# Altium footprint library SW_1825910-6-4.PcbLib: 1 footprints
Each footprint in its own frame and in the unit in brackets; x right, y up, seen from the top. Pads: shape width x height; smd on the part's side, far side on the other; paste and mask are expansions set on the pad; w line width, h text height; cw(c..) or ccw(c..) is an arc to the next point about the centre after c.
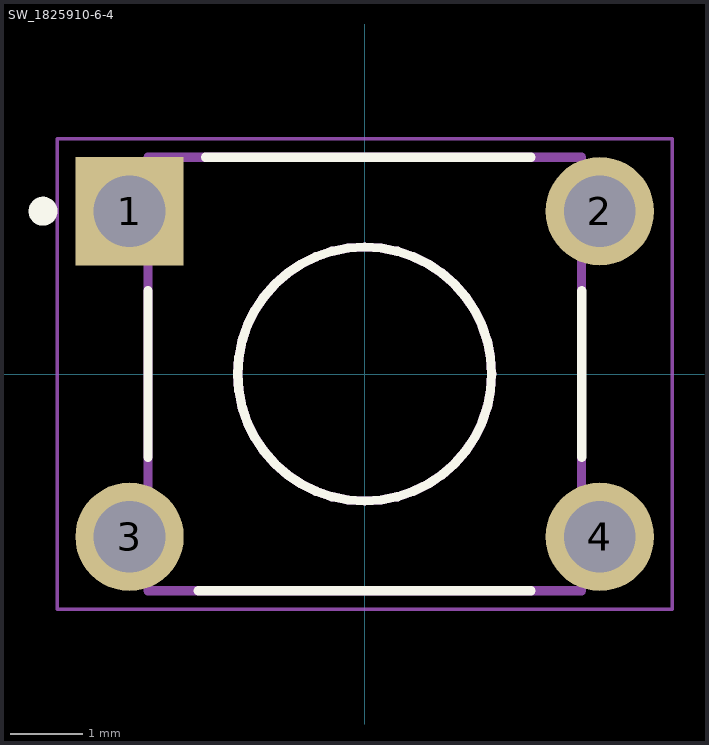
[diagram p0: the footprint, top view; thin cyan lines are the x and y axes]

## SW_1825910-6-4 [mm]
pads (4):
  rect 1.498x1.498 / inner round 1.498 / far side rect 1.498x1.498 hole 0.99 mask+0.102: 1(-3.25,2.25)
  round 1.498 hole 0.99 mask+0.102: 2(3.25,2.25) 3(-3.25,-2.25) 4(3.25,-2.25)
Top Overlay:
  circle w0.2: c-4.445,2.25 r0.1
  circle w0.127: c0,0 r1.755
  lines w0.127: -2.995,-1.15 -2.995,1.15 ; -2.3,-2.995 2.3,-2.995 ; -2.2,2.995 2.3,2.995 ; 3,-1.15 3,1.15
Assembly Top:
  circle w0.127: c0,0 r1.755
  lines w0.127: -2.995,-2.995 2.995,-2.995 2.995,2.995 -2.995,2.995 -2.995,-2.995
Courtyard Top:
  lines w0.05: -4.25,-3.25 4.25,-3.25 4.25,3.25 -4.25,3.25 -4.25,-3.25
3D body "step_temp.STEP": height 3.9, standoff -3.9, extent -2.995,0 2.995,8.51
